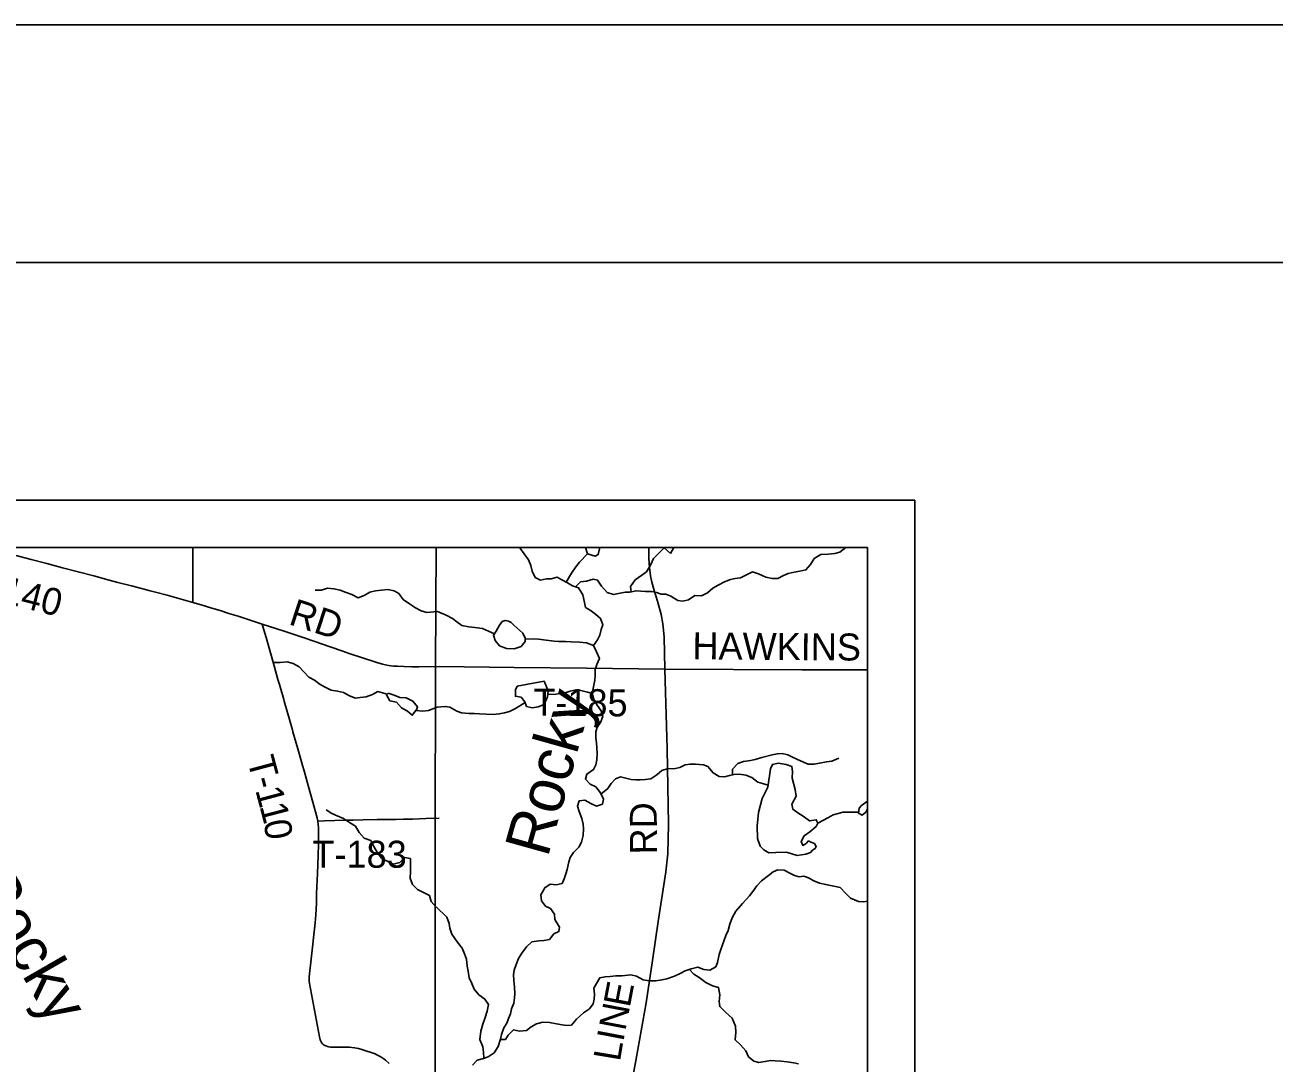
# Model space of a CAD drawing. Extents: x 0 to 34, y 0 to 22.
# Drawn here: x 7.127 to 9.758, y 19.815 to 22 of the extents above; entities that cross this region are included whole.
import ezdxf

# ---------------------------------------------------------------- set-up
doc = ezdxf.new("R2010")
doc.units = 0
for name, color, linetype in [('GM_X_Corporation', 7, 'Continuous'), ('GM_X_County_Road', 7, 'Continuous'), ('GM_X_County_Road_Text', 7, 'Continuous'), ('GM_X_Minor_Lake', 7, 'Continuous'), ('GM_X_Minor_River', 7, 'Continuous'), ('GM_X_Minor_River_Text', 7, 'Continuous'), ('GM_X_Township_Road', 7, 'Continuous'), ('GM_X_Township_Road_Text', 7, 'Continuous'), ('SH_Border', 7, 'Continuous'), ('SH_Cut_Line', 7, 'Continuous'), ('SH_Data', 7, 'Continuous')]:
    doc.layers.add(name, color=color, linetype=linetype)

msp = doc.modelspace()

# ---------------------------------------------------------------- linework, layer by layer
at = {"layer": 'GM_X_Corporation'}
for points in [[(7.991, 17.7727), (7.9901, 18.1613), (7.988, 19.001), (7.9884, 19.0254), (7.9898, 19.1149), (7.9901, 19.6615), (7.9904, 20.2824), (7.9906, 20.6512), (7.9922, 20.9), (2.1, 20.9), (2.1, 14.1)], [(8.9, 14.1), (8.9, 20.9), (7.9922, 20.9), (7.9906, 20.6512), (7.9904, 20.2824), (7.9901, 19.6615), (7.9898, 19.1149), (7.9884, 19.0254), (7.988, 19.001), (7.9901, 18.1613), (7.991, 17.7727)]]:
    msp.add_lwpolyline(points, dxfattribs=at)
for points in [[(7.9922, 20.9), (2.8099, 20.9), (2.8107, 20.774), (2.8158, 19.9868), (2.8247, 19.0323), (3.279, 19.0395), (3.3208, 19.0402), (3.8964, 19.0508), (4.1999, 19.0575), (4.5008, 19.0629), (4.7704, 19.0672), (4.9094, 19.0728), (5.4081, 19.0763), (6.7986, 19.0964), (7.9898, 19.1149), (7.9901, 19.6615), (7.9904, 20.2824), (7.9906, 20.6512)], [(8.9, 19.1229), (8.9, 20.9), (7.9922, 20.9), (7.9906, 20.6512), (7.9904, 20.2824), (7.9901, 19.6615), (7.9898, 19.1149), (8.1319, 19.1166), (8.1678, 19.1165), (8.3772, 19.1188)]]:
    msp.add_lwpolyline(points, close=True, dxfattribs=at)
at = {"layer": 'GM_X_County_Road'}
msp.add_lwpolyline([(8.3924, 19.7104), (8.4132, 19.8235), (8.4339, 19.9414), (8.4476, 20.0305), (8.4598, 20.1127), (8.4753, 20.2174), (8.4796, 20.2557), (8.481, 20.3175), (8.4781, 20.4761), (8.4737, 20.644), (8.4722, 20.7119), (8.4695, 20.7398), (8.4657, 20.7591), (8.4583, 20.787), (8.4513, 20.8095), (8.4462, 20.8274), (8.4431, 20.8404), (8.441, 20.8583), (8.4397, 20.877), (8.4399, 20.9)], dxfattribs=at)
at = {"layer": 'GM_X_Minor_Lake'}
for p, q in [((8.4711, 20.9), (8.4852, 20.8878)), ((8.4852, 20.8878), (8.4924, 20.9)), ((8.9, 20.3664), (8.8876, 20.3569))]:
    msp.add_line(p, q, dxfattribs=at)
for points in [[(8.3067, 20.9), (8.311, 20.8865), (8.3266, 20.8817), (8.3334, 20.8852), (8.3363, 20.8974), (8.337, 20.9)], [(8.1309, 20.7442), (8.1253, 20.7366), (8.1182, 20.724), (8.1129, 20.7156), (8.1161, 20.7046), (8.1257, 20.6933), (8.1405, 20.6877), (8.1561, 20.6871), (8.1708, 20.6918), (8.1795, 20.7021), (8.1794, 20.7093), (8.1744, 20.7196)], [(8.1744, 20.7196), (8.1554, 20.7368), (8.1499, 20.7423), (8.1448, 20.7451), (8.1377, 20.7466), (8.1309, 20.7442)], [(8.1628, 20.6085), (8.1591, 20.6009), (8.1589, 20.5872), (8.171, 20.5854), (8.1787, 20.5752), (8.1826, 20.5657), (8.194, 20.5628), (8.2069, 20.5645), (8.2194, 20.5699), (8.2268, 20.5855), (8.2278, 20.5985), (8.2197, 20.6185)], [(8.2197, 20.6185), (8.1628, 20.6085)], [(7.8911, 20.5935), (7.8876, 20.5901), (7.8949, 20.5772), (7.9086, 20.5747), (7.919, 20.563), (7.9317, 20.5555), (7.942, 20.5469), (7.9518, 20.56)], [(7.9518, 20.56), (7.9529, 20.5645), (7.9428, 20.577), (7.9291, 20.584), (7.9161, 20.5847), (7.9039, 20.5891), (7.891, 20.5935)], [(7.9518, 20.56), (7.9529, 20.5645), (7.9428, 20.577), (7.9291, 20.584), (7.9161, 20.5847), (7.9039, 20.5891), (7.8911, 20.5935)], [(8.6903, 20.3957), (8.6784, 20.3717), (8.6707, 20.3424), (8.6679, 20.3138), (8.6685, 20.2876), (8.6744, 20.2717), (8.6817, 20.2638), (8.6927, 20.2578), (8.7075, 20.258), (8.7299, 20.2586), (8.752, 20.2519), (8.7705, 20.2548), (8.7804, 20.2583), (8.7841, 20.2629), (8.7898, 20.2664), (8.7924, 20.2709), (8.7885, 20.2774), (8.7809, 20.2799), (8.776, 20.2826), (8.7707, 20.2772), (8.7639, 20.273), (8.7608, 20.2813), (8.7671, 20.2935), (8.7788, 20.302), (8.792, 20.3131), (8.7958, 20.3196), (8.7923, 20.3272), (8.7783, 20.3248), (8.7645, 20.3345), (8.7534, 20.342), (8.7431, 20.3491), (8.7411, 20.3601), (8.7497, 20.3765), (8.7477, 20.3906), (8.7414, 20.4145), (8.7424, 20.4285), (8.7408, 20.4395), (8.7286, 20.4436), (8.7119, 20.4461), (8.6998, 20.4437), (8.6957, 20.4346)], [(8.6957, 20.4346), (8.6903, 20.3957)], [(8.8876, 20.3569), (8.8827, 20.3516), (8.8809, 20.3413), (8.8886, 20.3368), (8.8969, 20.3434), (8.9, 20.3493)]]:
    msp.add_lwpolyline(points, dxfattribs=at)
at = {"layer": 'GM_X_Minor_River'}
for points in [[(8.1684, 20.9), (8.1682, 20.8996), (8.1778, 20.8868), (8.1863, 20.8739), (8.1913, 20.8622), (8.1944, 20.8501), (8.2006, 20.8372), (8.2117, 20.8316), (8.2246, 20.8344), (8.2341, 20.8341), (8.2469, 20.8377), (8.2565, 20.8324), (8.2687, 20.8261), (8.2793, 20.8197), (8.2919, 20.8153), (8.3008, 20.8002), (8.3047, 20.7842), (8.3067, 20.774), (8.3162, 20.768), (8.3273, 20.7598), (8.3384, 20.7507), (8.3431, 20.7371), (8.3394, 20.7276), (8.3364, 20.7154), (8.332, 20.7058), (8.3234, 20.6936), (8.3299, 20.6804), (8.3357, 20.6667), (8.3305, 20.6542), (8.3272, 20.6435), (8.3266, 20.6309), (8.3259, 20.6207), (8.3234, 20.607), (8.3209, 20.5918), (8.3248, 20.5785), (8.3309, 20.5683)], [(8.2852, 20.8177), (8.2963, 20.8279), (8.3085, 20.8291), (8.3225, 20.8338), (8.332, 20.8316), (8.3401, 20.8188), (8.352, 20.8056), (8.3653, 20.8015), (8.3793, 20.804), (8.3903, 20.8063), (8.3998, 20.806), (8.413, 20.8092), (8.4233, 20.8082), (8.4328, 20.8075), (8.4464, 20.8072), (8.4559, 20.8054), (8.4658, 20.8021), (8.4757, 20.8022), (8.486, 20.7977), (8.5012, 20.7888), (8.5115, 20.7873), (8.5236, 20.7901), (8.5364, 20.7994), (8.5509, 20.7984), (8.563, 20.8049), (8.5746, 20.8145), (8.5856, 20.8211), (8.5988, 20.8277), (8.6117, 20.8331), (8.6219, 20.8347), (8.6329, 20.8364), (8.6453, 20.8429), (8.6578, 20.8491), (8.6707, 20.8447), (8.686, 20.838), (8.6997, 20.8347), (8.7111, 20.8352), (8.7231, 20.841), (8.7334, 20.8457), (8.7458, 20.8484), (8.7576, 20.8501), (8.7705, 20.8529), (8.7802, 20.8647), (8.7881, 20.877), (8.8017, 20.8851), (8.8172, 20.8864), (8.8313, 20.8876), (8.8422, 20.89), (8.8543, 20.9)], [(8.4026, 20.8067), (8.4016, 20.8182), (8.4113, 20.832), (8.4249, 20.842), (8.4347, 20.8486), (8.4444, 20.8646), (8.4496, 20.8772), (8.4719, 20.8993)], [(8.2662, 20.8274), (8.2768, 20.8463), (8.2862, 20.8597), (8.2937, 20.8693), (8.3109, 20.8868)], [(7.9953, 20.7657), (7.9729, 20.7633), (7.9608, 20.767), (7.949, 20.7735), (7.936, 20.7818), (7.9231, 20.791), (7.9135, 20.8035), (7.904, 20.8092), (7.8903, 20.8118), (7.8774, 20.8107), (7.8644, 20.8088), (7.8523, 20.8061), (7.8405, 20.7988), (7.8279, 20.7943), (7.815, 20.8011), (7.8028, 20.8053), (7.7899, 20.8102), (7.7769, 20.8132), (7.7632, 20.8147), (7.7511, 20.8105), (7.7377, 20.8101)], [(8.1149, 20.7187), (8.09, 20.7294), (8.0737, 20.7319), (8.0612, 20.7333), (8.0463, 20.7362), (8.036, 20.7437), (8.0265, 20.7508), (8.0135, 20.7579), (7.9953, 20.7657)], [(8.3234, 20.6936), (8.3089, 20.6992), (8.2941, 20.7009), (8.2762, 20.7015), (8.2645, 20.7022), (8.2504, 20.7024), (8.2405, 20.7031), (8.2238, 20.7052), (8.2075, 20.707), (8.1961, 20.708), (8.1794, 20.707)], [(7.8888, 20.5914), (7.8693, 20.5969), (7.8579, 20.5905), (7.845, 20.5855), (7.832, 20.5847), (7.8225, 20.5832), (7.8096, 20.5877), (7.797, 20.5949), (7.7848, 20.598), (7.7711, 20.6002), (7.7597, 20.6052), (7.7479, 20.6116), (7.7365, 20.6211), (7.7239, 20.6275), (7.7136, 20.6386), (7.7041, 20.6492), (7.6915, 20.656), (7.6786, 20.6594), (7.6638, 20.6579), (7.6501, 20.6579)], [(8.3211, 20.593), (8.3106, 20.5955), (8.2965, 20.5995), (8.2866, 20.6009), (8.2741, 20.5981), (8.2635, 20.5946), (8.2537, 20.5926), (8.2442, 20.5914), (8.2272, 20.5905)], [(7.9946, 20.5642), (7.9763, 20.5568), (7.9641, 20.556), (7.9495, 20.5569)], [(8.1793, 20.5738), (8.1595, 20.5613), (8.1466, 20.5551), (8.136, 20.5524), (8.125, 20.55), (8.1125, 20.5487), (8.0973, 20.549), (8.0833, 20.55), (8.0719, 20.5506), (8.0609, 20.5509), (8.0457, 20.5523), (8.0354, 20.5556), (8.0209, 20.5638), (8.0114, 20.5656), (7.9946, 20.5642)], [(8.3309, 20.5683), (8.3398, 20.5566), (8.3429, 20.5445), (8.3381, 20.5319), (8.3313, 20.5223), (8.328, 20.5124), (8.3285, 20.4987), (8.3298, 20.4889), (8.3306, 20.4786), (8.3311, 20.4665), (8.3304, 20.4535), (8.3283, 20.4425), (8.3234, 20.4326), (8.3091, 20.4229), (8.3065, 20.4126), (8.3161, 20.4021), (8.3283, 20.3961), (8.3379, 20.3837), (8.3445, 20.3705), (8.3423, 20.3602), (8.3298, 20.3559), (8.318, 20.3611), (8.3054, 20.3682), (8.2933, 20.3669), (8.2896, 20.3559), (8.2935, 20.3445), (8.2989, 20.3294), (8.3013, 20.318), (8.3022, 20.3081), (8.3015, 20.2937), (8.2979, 20.2796), (8.2926, 20.2696), (8.281, 20.2581), (8.2746, 20.2478), (8.2713, 20.2383), (8.268, 20.2227), (8.2654, 20.2132), (8.2617, 20.2025), (8.2573, 20.1926), (8.2448, 20.1902), (8.2319, 20.1916), (8.2209, 20.1839), (8.2123, 20.169), (8.214, 20.1561), (8.2224, 20.1455), (8.2327, 20.1403), (8.2415, 20.1282), (8.242, 20.1168), (8.252, 20.1013), (8.2506, 20.0918), (8.24, 20.0871), (8.2306, 20.0749), (8.2189, 20.0729), (8.2086, 20.0724), (8.1939, 20.07), (8.1822, 20.0596), (8.1728, 20.0462), (8.1653, 20.0348), (8.1609, 20.0222), (8.1565, 20.0107), (8.155, 20.0009), (8.1555, 19.9895), (8.1568, 19.975), (8.1577, 19.9617), (8.1574, 19.9522), (8.1559, 19.9408), (8.1511, 19.9294), (8.1486, 19.9187), (8.1448, 19.9088), (8.1408, 19.8989), (8.1348, 19.889), (8.13, 19.8749), (8.1278, 19.8653), (8.1226, 19.8497), (8.1144, 19.8363), (8.1016, 19.8278), (8.0917, 19.8247), (8.0785, 19.8208), (8.0687, 19.8104)], [(8.3391, 20.3813), (8.3534, 20.3926), (8.3605, 20.4037), (8.3695, 20.4132), (8.3801, 20.4171), (8.3911, 20.4146), (8.4025, 20.412), (8.4124, 20.411), (8.4219, 20.4111), (8.4325, 20.4119), (8.4443, 20.4132), (8.4567, 20.4213), (8.4673, 20.4305), (8.4805, 20.4348), (8.4923, 20.4342), (8.5048, 20.4373), (8.5161, 20.4424), (8.5267, 20.4444), (8.5381, 20.4441), (8.5548, 20.4424), (8.5643, 20.439), (8.5751, 20.4258), (8.5881, 20.418), (8.5994, 20.4177), (8.6097, 20.4201), (8.6195, 20.4224), (8.6309, 20.4229), (8.6442, 20.4212), (8.6564, 20.4159), (8.669, 20.4062), (8.6793, 20.4036), (8.6909, 20.3998)], [(8.6159, 20.4216), (8.616, 20.4334), (8.6273, 20.4457), (8.6394, 20.4496), (8.6538, 20.4516), (8.664, 20.454), (8.6776, 20.4579), (8.6996, 20.4635), (8.7106, 20.4659), (8.7204, 20.4667), (8.7326, 20.4638), (8.7421, 20.4589), (8.7517, 20.4545), (8.7654, 20.4485), (8.7753, 20.4444), (8.7878, 20.4442), (8.7988, 20.4465), (8.8139, 20.449), (8.8253, 20.4502), (8.8397, 20.4568)], [(7.9931, 20.1427), (7.9818, 20.1552), (7.9784, 20.1673), (7.9658, 20.1738), (7.9529, 20.1806), (7.9426, 20.1905), (7.9372, 20.2042), (7.938, 20.2179), (7.9383, 20.2315), (7.9379, 20.2452), (7.9257, 20.2479), (7.9155, 20.2368), (7.9018, 20.2338), (7.8904, 20.2391), (7.8774, 20.2463), (7.8687, 20.2577), (7.8607, 20.2706), (7.8545, 20.2832), (7.8405, 20.2885), (7.8305, 20.3006), (7.8222, 20.3135), (7.81, 20.3211), (7.797, 20.3295), (7.7841, 20.3352), (7.7723, 20.3401), (7.7605, 20.3477)], [(8.7955, 20.3202), (8.818, 20.3316), (8.8279, 20.3374), (8.8381, 20.3405), (8.8479, 20.3429), (8.8612, 20.343), (8.8813, 20.3433)], [(8.1276, 19.8647), (8.138, 19.8643), (8.1436, 19.8738), (8.1553, 19.885), (8.1679, 19.8824), (8.1823, 19.8837), (8.1924, 19.891), (8.2034, 19.8972), (8.2166, 19.9011), (8.2311, 19.9005), (8.2455, 19.8976), (8.2577, 19.8954), (8.2672, 19.894), (8.277, 19.8949), (8.2875, 19.9075), (8.3026, 19.9209), (8.3147, 19.929), (8.3229, 19.9394), (8.3251, 19.9496), (8.3254, 19.9603), (8.3241, 19.9728), (8.3297, 19.9824), (8.3365, 19.9946), (8.3478, 19.9966), (8.3585, 19.9975), (8.3702, 19.9983), (8.3831, 19.9988), (8.4017, 20.0005), (8.4142, 19.9976), (8.4276, 19.9901), (8.4405, 19.9883), (8.4549, 19.9881), (8.4674, 19.9901), (8.4777, 19.9925), (8.4939, 19.9976), (8.506, 20.0034), (8.5166, 20.0088), (8.5291, 20.0135), (8.5427, 20.0171), (8.5557, 20.0122), (8.5682, 20.0104), (8.5806, 20.0174), (8.5847, 20.0269), (8.588, 20.0433), (8.5913, 20.054), (8.5947, 20.0635), (8.5984, 20.0738), (8.6021, 20.0833), (8.6069, 20.094), (8.6102, 20.1074), (8.615, 20.1207), (8.6229, 20.1345), (8.6371, 20.1509), (8.6518, 20.1666), (8.6585, 20.1762), (8.6675, 20.1881), (8.6773, 20.1988), (8.692, 20.2096), (8.7018, 20.2177), (8.7116, 20.2215), (8.7245, 20.2213), (8.7367, 20.2146), (8.7463, 20.2097), (8.7562, 20.2071), (8.7664, 20.2084), (8.7759, 20.2047), (8.787, 20.1983), (8.7988, 20.1939), (8.8121, 20.1906), (8.822, 20.1888), (8.833, 20.1866), (8.8425, 20.1848), (8.8548, 20.172), (8.864, 20.1618), (8.8815, 20.1547), (8.8921, 20.1545), (8.9, 20.1559)], [(8.0927, 19.825), (8.092, 19.8376), (8.0907, 19.849), (8.0842, 19.8642), (8.0863, 19.8824), (8.0903, 19.8965), (8.0951, 19.911), (8.0996, 19.924), (8.1025, 19.9384), (8.0944, 19.9494), (8.0818, 19.9587), (8.0722, 19.9708), (8.0672, 19.9825), (8.0614, 19.9943), (8.0593, 20.0083), (8.0577, 20.0189), (8.0561, 20.0337), (8.0522, 20.0451), (8.0471, 20.0568), (8.0364, 20.07), (8.0252, 20.0863), (8.0213, 20.0991), (8.0193, 20.109), (8.0147, 20.1223), (7.9931, 20.1428)], [(8.5255, 20.0122), (8.5345, 20.0018), (8.5456, 19.9947), (8.5597, 19.9845), (8.5738, 19.9774), (8.5867, 19.9738), (8.5895, 19.9586), (8.5878, 19.9445), (8.589, 19.9339), (8.6012, 19.9222), (8.615, 19.9094), (8.6224, 19.8928), (8.6233, 19.8795), (8.6219, 19.8639), (8.633, 19.853), (8.6441, 19.8406), (8.6499, 19.8281), (8.661, 19.8187), (8.6713, 19.8161), (8.6841, 19.8181), (8.6966, 19.8205), (8.7061, 19.8199), (8.7179, 19.8188), (8.7308, 19.8178), (8.7449, 19.8157), (8.7551, 19.8135)]]:
    msp.add_lwpolyline(points, dxfattribs=at)
at = {"layer": 'GM_X_Township_Road'}
for points in [[(7.0434, 20.9), (7.0836, 20.8896), (7.1399, 20.8748), (7.1727, 20.8663), (7.2055, 20.8576), (7.2387, 20.8489), (7.272, 20.8404), (7.3043, 20.8317), (7.3222, 20.8268), (7.3507, 20.8194), (7.3747, 20.813), (7.3906, 20.8088), (7.4016, 20.806), (7.4263, 20.7995), (7.4799, 20.7846), (7.4973, 20.7796), (7.5199, 20.7727), (7.5373, 20.7673), (7.5561, 20.7615), (7.5753, 20.7553), (7.626, 20.7391)], [(7.4799, 20.7846), (7.4801, 20.8741), (7.4804, 20.8989), (7.4804, 20.9)], [(7.8931, 19.8141), (7.8854, 19.8209), (7.8821, 19.8235), (7.8776, 19.8266), (7.8732, 19.8293), (7.8671, 19.8325), (7.8635, 19.8341), (7.8358, 19.8433), (7.8288, 19.8453), (7.8207, 19.8471), (7.8147, 19.8479), (7.8098, 19.8482), (7.7831, 19.8483), (7.7699, 19.8486), (7.7663, 19.8491), (7.7632, 19.8497), (7.7598, 19.8509), (7.7566, 19.8525), (7.7545, 19.854), (7.7527, 19.8557), (7.7508, 19.8584), (7.7493, 19.861), (7.7481, 19.864), (7.7472, 19.8673), (7.7466, 19.87), (7.7258, 19.9824), (7.7251, 19.9875), (7.7249, 19.9908), (7.7248, 19.9937), (7.7249, 19.9962), (7.7254, 20.0025), (7.7288, 20.0339), (7.7375, 20.1098), (7.7391, 20.1269), (7.7402, 20.1515), (7.7407, 20.1719), (7.7426, 20.2137), (7.7439, 20.2521), (7.7445, 20.2756), (7.7446, 20.2859), (7.7447, 20.2967), (7.7448, 20.3026), (7.7447, 20.3099), (7.7442, 20.3173), (7.7433, 20.3243), (7.7425, 20.3278), (7.7417, 20.3312), (7.7405, 20.3361), (7.7329, 20.3641), (7.7229, 20.3989), (7.7141, 20.43), (7.7109, 20.4412), (7.7052, 20.4613), (7.7008, 20.4766), (7.6906, 20.5125), (7.6896, 20.5161), (7.6876, 20.5231), (7.6804, 20.5481), (7.6799, 20.55), (7.6723, 20.5767), (7.6713, 20.5802), (7.6623, 20.6121), (7.66, 20.62), (7.6593, 20.6225), (7.6512, 20.6511), (7.6357, 20.7058), (7.626, 20.7391)], [(7.626, 20.7391), (7.6723, 20.7238), (7.7103, 20.7111), (7.7391, 20.7014), (7.7486, 20.6981), (7.7936, 20.6828), (7.8092, 20.6773), (7.8628, 20.6593), (7.8676, 20.6579), (7.8793, 20.6547), (7.8881, 20.6527), (7.8923, 20.6519), (7.8966, 20.6514), (7.9027, 20.6507), (7.9106, 20.6501), (7.9241, 20.6494), (7.9411, 20.6492), (7.9558, 20.6491), (7.9989, 20.6494)], [(7.9989, 20.6494), (8.1565, 20.6477), (8.3087, 20.6464), (8.4737, 20.644)], [(8.4737, 20.644), (8.7619, 20.6426), (8.9, 20.6426)], [(7.7433, 20.3243), (7.7571, 20.3247), (7.8004, 20.3261), (7.8178, 20.3264), (7.8387, 20.3266), (7.8679, 20.3273), (7.8951, 20.3276), (7.9073, 20.3277), (7.9232, 20.328), (7.9425, 20.3285), (7.9709, 20.3294), (7.9987, 20.3301)]]:
    msp.add_lwpolyline(points, dxfattribs=at)
at = {"layer": 'SH_Border'}
msp.add_lwpolyline([(1.5, 21.5), (33.5, 21.5), (33.5, 0.5), (1.5, 0.5)], close=True, dxfattribs=at)
at = {"layer": 'SH_Cut_Line'}
msp.add_lwpolyline([(0, 0), (34, 0), (34, 22), (0, 22)], close=True, dxfattribs=at)
at = {"layer": 'SH_Data'}
for p, q in [((2, 21), (9, 21)), ((9, 21), (9, 14)), ((2.1, 20.9), (8.9, 20.9)), ((8.9, 20.9), (8.9, 14.1))]:
    msp.add_line(p, q, dxfattribs=at)

# ---------------------------------------------------------------- texts
at = {"layer": 'GM_X_County_Road_Text'}
for s, height, rotation, p in [('RD', 0.05682, 90.4221, (8.4572, 20.2543)), ('E', 0.0568, 79.1876, (8.3997, 19.9303)), ('N', 0.0568, 79.1901, (8.3903, 19.8812)), ('I', 0.0568, 79.307, (8.386, 19.8583)), ('L', 0.0568, 80.513, (8.379, 19.8167))]:
    msp.add_text(s, height=height, rotation=rotation, dxfattribs=at).set_placement(p)
at = {"layer": 'GM_X_Minor_River_Text'}
for height, rotation, p in [(0.09475, 74.3271, (8.2268, 20.2456)), (0.09474, 299.9806, (7.007, 20.1954))]:
    msp.add_text('Rocky', height=height, rotation=rotation, dxfattribs=at).set_placement(p)
at = {"layer": 'GM_X_Township_Road_Text'}
for s, height, rotation, p in [('T-140', 0.05682, 345.6951, (7.0042, 20.8033)), ('RD', 0.05682, 341.8786, (7.6796, 20.7393)), ('HAWKINS', 0.05682, 359.5648, (8.5315, 20.6648)), ('T-185', 0.05682, 359.4355, (8.1964, 20.5464)), ('T', 0.0568, 285.0476, (7.5941, 20.4533)), ('1', 0.0568, 284.9539, (7.6112, 20.3897)), ('-', 0.0568, 285.0265, (7.6051, 20.4122)), ('1', 0.0568, 284.5992, (7.6202, 20.356)), ('0', 0.0568, 279.0662, (7.6287, 20.3236)), ('T-183', 0.05682, 0, (7.7318, 20.2261))]:
    msp.add_text(s, height=height, rotation=rotation, dxfattribs=at).set_placement(p)

doc.saveas('drawing.dxf')
